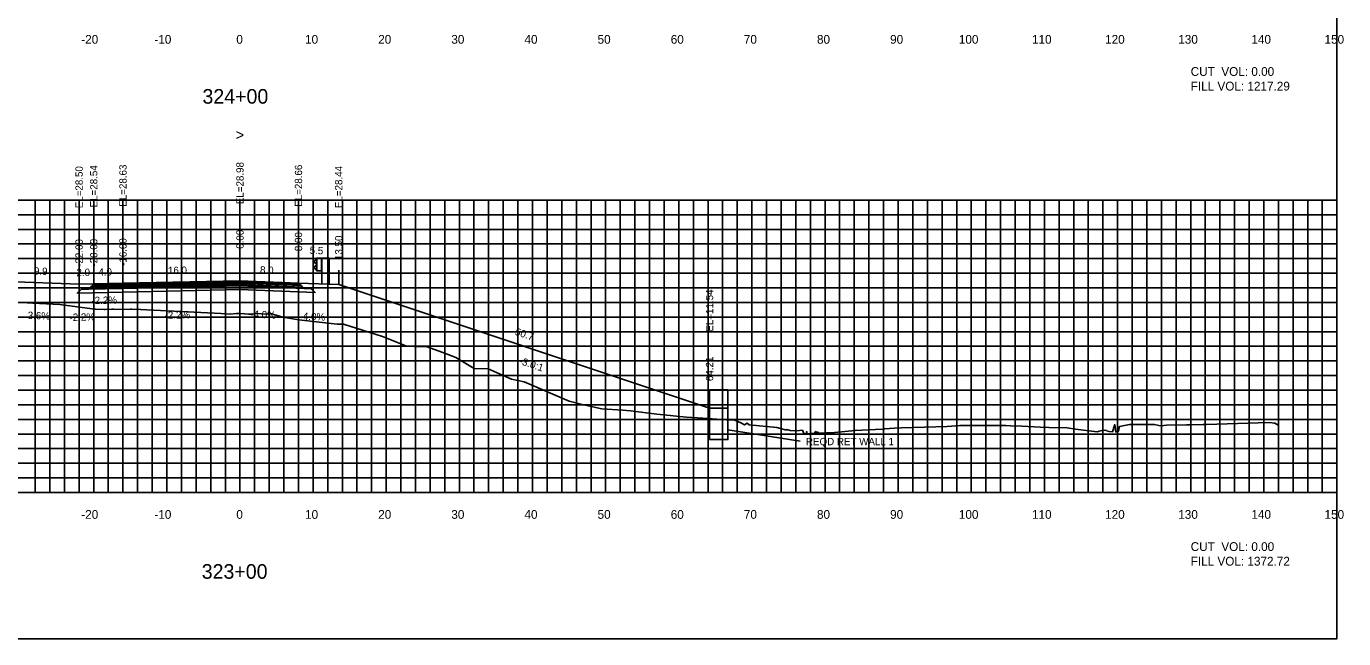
# Model space of a CAD drawing. Extents: x 1797652 to 1804145, y 245981 to 250269.
# Drawn here: x 1803621.8 to 1803801.9, y 250079.4 to 250163.2 of the extents above; entities that cross this region are included whole.
import ezdxf

# ---------------------------------------------------------------- set-up
doc = ezdxf.new("R2010")
doc.units = 0
for name, color, linetype in [('1', 7, 'Continuous'), ('10', 7, 'Continuous'), ('3', 7, 'Continuous'), ('4', 7, 'Continuous'), ('60', 7, 'Continuous'), ('ANNO-TXT', 7, 'Continuous'), ('BASE', 7, 'Continuous'), ('CL-CNST', 7, 'Continuous'), ('Level 1', 7, 'Continuous'), ('Level 62', 7, 'Continuous'), ('LOWER BINDER', 7, 'Continuous'), ('M-ROADS', 7, 'Continuous'), ('UPPER BINDER', 7, 'Continuous'), ('WEARING', 7, 'Continuous')]:
    doc.layers.add(name, color=color, linetype=linetype)

msp = doc.modelspace()

# ---------------------------------------------------------------- linework, layer by layer
for p, q in [((1803631, 250127.97), (1803631, 250129.97)), ((1803635, 250128.06), (1803635, 250130.06)), ((1803651, 250128.41), (1803651, 250130.41)), ((1803659, 250128.09), (1803659, 250130.09)), ((1803629, 250127.93), (1803629, 250129.93)), ((1803664.5, 250127.87), (1803664.5, 250129.87)), ((1803715.21, 250110.97), (1803715.21, 250112.97))]:
    msp.add_line(p, q)
msp.add_lwpolyline([(1803501, 250079.43), (1803801, 250079.43), (1803801, 250269.43), (1803501, 250269.43)], close=True)
at = {"layer": '3'}
msp.add_line((1803727.6, 250106.45), (1803717.71, 250108.02), dxfattribs=at)
at = {"layer": '60'}
for p, q in [((1803801, 250099.43), (1803801, 250139.43)), ((1803801.06, 250139.43), (1803801, 250139.43)), ((1803801.06, 250129.43), (1803801, 250129.43)), ((1803801.06, 250119.43), (1803801, 250119.43)), ((1803801.06, 250109.43), (1803801, 250109.43)), ((1803501, 250099.43), (1803801, 250099.43)), ((1803631, 250099.37), (1803631, 250099.43)), ((1803641, 250099.37), (1803641, 250099.43)), ((1803651, 250099.37), (1803651, 250099.43)), ((1803661, 250099.37), (1803661, 250099.43)), ((1803671, 250099.37), (1803671, 250099.43)), ((1803681, 250099.37), (1803681, 250099.43)), ((1803691, 250099.37), (1803691, 250099.43)), ((1803701, 250099.37), (1803701, 250099.43)), ((1803711, 250099.37), (1803711, 250099.43)), ((1803721, 250099.37), (1803721, 250099.43)), ((1803731, 250099.37), (1803731, 250099.43)), ((1803741, 250099.37), (1803741, 250099.43)), ((1803751, 250099.37), (1803751, 250099.43)), ((1803761, 250099.37), (1803761, 250099.43)), ((1803771, 250099.37), (1803771, 250099.43)), ((1803781, 250099.37), (1803781, 250099.43)), ((1803791, 250099.37), (1803791, 250099.43)), ((1803801, 250099.37), (1803801, 250099.43)), ((1803801.06, 250099.43), (1803801, 250099.43))]:
    msp.add_line(p, q, dxfattribs=at)
at = {"layer": 'BASE'}
msp.add_lwpolyline([(1803629.27, 250127.21), (1803630.27, 250127.24), (1803635, 250127.34), (1803651, 250127.69), (1803659.75, 250127.34), (1803660.75, 250127.3), (1803661.27, 250126.78), (1803651, 250127.19), (1803635, 250126.84), (1803628.75, 250126.7)], close=True, dxfattribs=at)
at = {"layer": 'CL-CNST'}
msp.add_lwpolyline([(1803619.11, 250128.28), (1803629, 250127.93), (1803631, 250127.97), (1803635, 250128.06), (1803651, 250128.41), (1803659, 250128.09), (1803664.5, 250127.87), (1803715.21, 250110.97)], dxfattribs=at)
for points in [[(1803717.71, 250110.97), (1803715.21, 250110.97), (1803715.21, 250113.47), (1803717.71, 250113.47)], [(1803715.21, 250106.68), (1803717.71, 250106.68), (1803717.71, 250110.97), (1803715.21, 250110.97)]]:
    msp.add_lwpolyline(points, close=True, dxfattribs=at)
at = {"layer": 'Level 1'}
for p, q in [((1803661.46, 250131.34), (1803661.1, 250131.04)), ((1803661.1, 250130.97), (1803661.46, 250130.68)), ((1803661.46, 250130.54), (1803661.1, 250130.24)), ((1803661.1, 250130.17), (1803661.46, 250129.89)), ((1803661.46, 250131.49), (1803661.46, 250129.74)), ((1803663.21, 250131.49), (1803661.46, 250131.49)), ((1803661.51, 250131.49), (1803661.51, 250129.74)), ((1803662.16, 250131.49), (1803662.16, 250129.74)), ((1803662.21, 250131.49), (1803662.21, 250127.96)), ((1803663.21, 250131.49), (1803663.21, 250127.92)), ((1803662.21, 250129.74), (1803661.46, 250129.74))]:
    msp.add_line(p, q, dxfattribs=at)
for centre in [(1803661.13, 250131), (1803661.13, 250130.21)]:
    msp.add_arc(centre, 0.05, 135, 226.6208, dxfattribs=at)
at = {"layer": 'Level 62'}
for p, q in [((1803501, 250139.43), (1803801, 250139.43)), ((1803623, 250099.43), (1803623, 250139.43)), ((1803625, 250099.43), (1803625, 250139.43)), ((1803627, 250099.43), (1803627, 250139.43)), ((1803629, 250099.43), (1803629, 250139.43)), ((1803631, 250099.43), (1803631, 250139.43)), ((1803633, 250099.43), (1803633, 250139.43)), ((1803635, 250099.43), (1803635, 250139.43)), ((1803637, 250099.43), (1803637, 250139.43)), ((1803639, 250099.43), (1803639, 250139.43)), ((1803641, 250099.43), (1803641, 250139.43)), ((1803643, 250099.43), (1803643, 250139.43)), ((1803645, 250099.43), (1803645, 250139.43)), ((1803647, 250099.43), (1803647, 250139.43)), ((1803649, 250099.43), (1803649, 250139.43)), ((1803651, 250099.43), (1803651, 250139.43)), ((1803653, 250099.43), (1803653, 250139.43)), ((1803655, 250099.43), (1803655, 250139.43)), ((1803657, 250099.43), (1803657, 250139.43)), ((1803659, 250099.43), (1803659, 250139.43)), ((1803661, 250099.43), (1803661, 250139.43)), ((1803663, 250099.43), (1803663, 250139.43)), ((1803665, 250099.43), (1803665, 250139.43)), ((1803667, 250099.43), (1803667, 250139.43)), ((1803669, 250099.43), (1803669, 250139.43)), ((1803671, 250099.43), (1803671, 250139.43)), ((1803673, 250099.43), (1803673, 250139.43)), ((1803675, 250099.43), (1803675, 250139.43)), ((1803677, 250099.43), (1803677, 250139.43)), ((1803679, 250099.43), (1803679, 250139.43)), ((1803681, 250099.43), (1803681, 250139.43)), ((1803683, 250099.43), (1803683, 250139.43)), ((1803685, 250099.43), (1803685, 250139.43)), ((1803687, 250099.43), (1803687, 250139.43)), ((1803689, 250099.43), (1803689, 250139.43)), ((1803691, 250099.43), (1803691, 250139.43)), ((1803693, 250099.43), (1803693, 250139.43)), ((1803695, 250099.43), (1803695, 250139.43)), ((1803697, 250099.43), (1803697, 250139.43)), ((1803699, 250099.43), (1803699, 250139.43)), ((1803701, 250099.43), (1803701, 250139.43)), ((1803703, 250099.43), (1803703, 250139.43)), ((1803705, 250099.43), (1803705, 250139.43)), ((1803707, 250099.43), (1803707, 250139.43)), ((1803709, 250099.43), (1803709, 250139.43)), ((1803711, 250099.43), (1803711, 250139.43)), ((1803713, 250099.43), (1803713, 250139.43)), ((1803715, 250099.43), (1803715, 250139.43)), ((1803717, 250099.43), (1803717, 250139.43)), ((1803719, 250099.43), (1803719, 250139.43)), ((1803721, 250099.43), (1803721, 250139.43)), ((1803723, 250099.43), (1803723, 250139.43)), ((1803725, 250099.43), (1803725, 250139.43)), ((1803727, 250099.43), (1803727, 250139.43)), ((1803729, 250099.43), (1803729, 250139.43)), ((1803731, 250099.43), (1803731, 250139.43)), ((1803733, 250099.43), (1803733, 250139.43)), ((1803735, 250099.43), (1803735, 250139.43)), ((1803737, 250099.43), (1803737, 250139.43)), ((1803739, 250099.43), (1803739, 250139.43)), ((1803741, 250099.43), (1803741, 250139.43)), ((1803743, 250099.43), (1803743, 250139.43)), ((1803745, 250099.43), (1803745, 250139.43)), ((1803747, 250099.43), (1803747, 250139.43)), ((1803749, 250099.43), (1803749, 250139.43)), ((1803751, 250099.43), (1803751, 250139.43)), ((1803753, 250099.43), (1803753, 250139.43)), ((1803755, 250099.43), (1803755, 250139.43)), ((1803757, 250099.43), (1803757, 250139.43)), ((1803759, 250099.43), (1803759, 250139.43)), ((1803761, 250099.43), (1803761, 250139.43)), ((1803763, 250099.43), (1803763, 250139.43)), ((1803765, 250099.43), (1803765, 250139.43)), ((1803767, 250099.43), (1803767, 250139.43)), ((1803769, 250099.43), (1803769, 250139.43)), ((1803771, 250099.43), (1803771, 250139.43)), ((1803773, 250099.43), (1803773, 250139.43)), ((1803775, 250099.43), (1803775, 250139.43)), ((1803777, 250099.43), (1803777, 250139.43)), ((1803779, 250099.43), (1803779, 250139.43)), ((1803781, 250099.43), (1803781, 250139.43)), ((1803783, 250099.43), (1803783, 250139.43)), ((1803785, 250099.43), (1803785, 250139.43)), ((1803787, 250099.43), (1803787, 250139.43)), ((1803789, 250099.43), (1803789, 250139.43)), ((1803791, 250099.43), (1803791, 250139.43)), ((1803793, 250099.43), (1803793, 250139.43)), ((1803795, 250099.43), (1803795, 250139.43)), ((1803797, 250099.43), (1803797, 250139.43)), ((1803799, 250099.43), (1803799, 250139.43)), ((1803801, 250099.43), (1803801, 250139.43)), ((1803501, 250137.43), (1803801, 250137.43)), ((1803501, 250135.43), (1803801, 250135.43)), ((1803501, 250133.43), (1803801, 250133.43)), ((1803501, 250131.43), (1803801, 250131.43)), ((1803501, 250129.43), (1803801, 250129.43)), ((1803501, 250127.43), (1803801, 250127.43)), ((1803501, 250125.43), (1803801, 250125.43)), ((1803501, 250123.43), (1803801, 250123.43)), ((1803501, 250121.43), (1803801, 250121.43)), ((1803501, 250119.43), (1803801, 250119.43)), ((1803501, 250117.43), (1803801, 250117.43)), ((1803501, 250115.43), (1803801, 250115.43)), ((1803501, 250113.43), (1803801, 250113.43)), ((1803501, 250111.43), (1803801, 250111.43)), ((1803501, 250109.43), (1803801, 250109.43)), ((1803501, 250107.43), (1803801, 250107.43)), ((1803501, 250105.43), (1803801, 250105.43)), ((1803501, 250103.43), (1803801, 250103.43)), ((1803501, 250101.43), (1803801, 250101.43)), ((1803501, 250099.43), (1803801, 250099.43))]:
    msp.add_line(p, q, dxfattribs=at)
at = {"layer": 'LOWER BINDER'}
for points in [[(1803635, 250127.53), (1803651, 250127.88), (1803659.55, 250127.54), (1803659.75, 250127.34), (1803651, 250127.69), (1803635, 250127.34), (1803630.27, 250127.24), (1803630.46, 250127.43)], [(1803635, 250127.72), (1803651, 250128.07), (1803659.36, 250127.74), (1803659.55, 250127.54), (1803651, 250127.88), (1803635, 250127.53), (1803630.46, 250127.43), (1803630.65, 250127.62)]]:
    msp.add_lwpolyline(points, close=True, dxfattribs=at)
at = {"layer": 'M-ROADS'}
msp.add_lwpolyline([(1803617.94, 250125.62), (1803622.69, 250125.34), (1803626.38, 250125.15), (1803630.8, 250124.58), (1803631.2, 250124.53), (1803631.24, 250124.53), (1803632.45, 250124.47), (1803632.57, 250124.48), (1803633.5, 250124.52), (1803633.7, 250124.53), (1803634.94, 250124.47), (1803634.95, 250124.47), (1803636.05, 250124.53), (1803636.2, 250124.53), (1803637.39, 250124.48), (1803637.45, 250124.47), (1803638.27, 250124.43), (1803648.42, 250123.92), (1803649.05, 250123.87), (1803649.67, 250123.81), (1803650.51, 250123.9), (1803650.9, 250123.92), (1803651.64, 250123.86), (1803652.15, 250123.81), (1803652.7, 250123.84), (1803653.42, 250123.92), (1803653.95, 250123.88), (1803654.67, 250123.81), (1803655.18, 250123.9), (1803656.86, 250123.42), (1803659.03, 250123.04), (1803664.31, 250122.47), (1803664.74, 250122.47), (1803665.15, 250122.47), (1803670.47, 250120.79), (1803673.7, 250119.49), (1803674.81, 250119.42), (1803675.61, 250119.42), (1803676.45, 250119.42), (1803678.74, 250118.57), (1803680.52, 250117.9), (1803683.02, 250116.4), (1803684.95, 250116.33), (1803688.14, 250114.93), (1803689.84, 250114.55), (1803696, 250111.91), (1803697.77, 250111.45), (1803700.47, 250110.9), (1803703.35, 250110.7), (1803704.4, 250110.62), (1803708, 250110.16), (1803712.06, 250109.76), (1803714.28, 250109.61), (1803717.49, 250109.38), (1803718.58, 250109.38), (1803719.56, 250108.9), (1803719.99, 250108.69), (1803720.34, 250108.91), (1803720.62, 250108.69), (1803724.43, 250108.34), (1803725.73, 250107.96), (1803725.77, 250108.06), (1803726.23, 250107.92), (1803727.08, 250107.87), (1803727.91, 250107.96), (1803728.12, 250107.49), (1803728.44, 250107.47), (1803728.5, 250107.76), (1803728.51, 250107.48), (1803728.53, 250107.44), (1803729.13, 250107.49), (1803729.55, 250107.5), (1803729.68, 250107.78), (1803729.9, 250107.57), (1803729.98, 250107.72), (1803730.1, 250107.55), (1803732.28, 250107.66), (1803735.1, 250107.93), (1803737.89, 250108.04), (1803738.99, 250108.09), (1803739.12, 250108.14), (1803740.5, 250108.22), (1803741.44, 250108.27), (1803744.6, 250108.37), (1803747.68, 250108.48), (1803749.44, 250108.58), (1803754.15, 250108.58), (1803754.99, 250108.58), (1803755.48, 250108.59), (1803755.69, 250108.6), (1803755.69, 250108.6), (1803755.7, 250108.6), (1803755.72, 250108.6), (1803756.37, 250108.53), (1803757.91, 250108.49), (1803760.42, 250108.35), (1803761.58, 250108.33), (1803764.1, 250108.3), (1803765.23, 250108.1), (1803768.2, 250107.74), (1803768.49, 250107.81), (1803768.86, 250107.92), (1803769.26, 250107.97), (1803769.48, 250107.9), (1803769.5, 250107.88), (1803769.84, 250107.79), (1803770.3, 250107.73), (1803770.59, 250108.58), (1803770.62, 250108.72), (1803770.64, 250108.67), (1803770.75, 250107.71), (1803770.76, 250107.73), (1803770.79, 250107.75), (1803771.09, 250107.76), (1803771.14, 250107.87), (1803771.18, 250107.99), (1803771.23, 250108.31), (1803771.27, 250108.48), (1803772.65, 250108.72), (1803772.93, 250108.72), (1803774.21, 250108.72), (1803774.93, 250108.72), (1803775.69, 250108.72), (1803776.07, 250108.72), (1803776.63, 250108.61), (1803776.97, 250108.54), (1803777.68, 250108.64), (1803780.44, 250108.71), (1803780.97, 250108.71), (1803781, 250108.68), (1803781.06, 250108.71), (1803782.68, 250108.75), (1803783.14, 250108.75), (1803790.22, 250108.95), (1803791.82, 250108.99), (1803792.42, 250108.91), (1803792.51, 250108.91), (1803792.96, 250108.65)], dxfattribs=at)
at = {"layer": 'UPPER BINDER'}
msp.add_lwpolyline([(1803659.36, 250127.74), (1803659.16, 250127.94), (1803651, 250128.26), (1803635, 250127.91), (1803630.85, 250127.82), (1803630.65, 250127.62), (1803635, 250127.72), (1803651, 250128.07)], close=True, dxfattribs=at)
at = {"layer": 'WEARING'}
msp.add_lwpolyline([(1803659.16, 250127.94), (1803659, 250128.09), (1803651, 250128.41), (1803635, 250128.06), (1803631, 250127.97), (1803630.85, 250127.82), (1803635, 250127.91), (1803651, 250128.26)], close=True, dxfattribs=at)

# ---------------------------------------------------------------- texts
msp.add_text('-3.0:1', height=1, rotation=341.5652).set_placement((1803689.07, 250117.05))
at = {"layer": '1'}
for s, p in [('324+00', (1803645.87, 250152.63)), ('323+00', (1803645.77, 250087.63))]:
    msp.add_text(s, height=2, dxfattribs=at).set_placement(p)
at = {"layer": '10'}
for s, p in [('-20', (1803629.3, 250160.83)), ('-10', (1803639.3, 250160.83)), ('0', (1803650.5, 250160.83)), ('10', (1803659.9, 250160.83)), ('20', (1803669.9, 250160.83)), ('30', (1803679.9, 250160.83)), ('40', (1803689.9, 250160.83)), ('50', (1803699.9, 250160.83)), ('60', (1803709.9, 250160.83)), ('70', (1803719.9, 250160.83)), ('80', (1803729.9, 250160.83)), ('90', (1803739.9, 250160.83)), ('100', (1803749.3, 250160.83)), ('110', (1803759.3, 250160.83)), ('120', (1803769.3, 250160.83)), ('130', (1803779.3, 250160.83)), ('140', (1803789.3, 250160.83)), ('150', (1803799.3, 250160.83)), ('-20', (1803629.3, 250095.83)), ('-10', (1803639.3, 250095.83)), ('0', (1803650.5, 250095.83)), ('10', (1803659.9, 250095.83)), ('20', (1803669.9, 250095.83)), ('30', (1803679.9, 250095.83)), ('40', (1803689.9, 250095.83)), ('50', (1803699.9, 250095.83)), ('60', (1803709.9, 250095.83)), ('70', (1803719.9, 250095.83)), ('80', (1803729.9, 250095.83)), ('90', (1803739.9, 250095.83)), ('100', (1803749.3, 250095.83)), ('110', (1803759.3, 250095.83)), ('120', (1803769.3, 250095.83)), ('130', (1803779.3, 250095.83)), ('140', (1803789.3, 250095.83)), ('150', (1803799.3, 250095.83))]:
    msp.add_text(s, height=1.2, dxfattribs=at).set_placement(p)
at = {"layer": '3'}
for s, p in [('EL=28.98', (1803651.5, 250138.88)), ('EL=28.50', (1803629.5, 250138.32)), ('EL=28.54', (1803631.5, 250138.44)), ('EL=28.63', (1803635.5, 250138.53)), ('EL=28.66', (1803659.5, 250138.52)), ('EL=28.44', (1803665, 250138.34)), ('-22.00', (1803629.5, 250130.31)), ('-20.00', (1803631.5, 250130.35)), ('-16.00', (1803635.5, 250130.44)), ('0.00', (1803651.5, 250132.77)), ('8.00', (1803659.5, 250132.45)), ('13.50', (1803665, 250131.24)), ('EL=11.54', (1803715.71, 250121.44)), ('64.21', (1803715.71, 250114.67))]:
    msp.add_text(s, height=1, rotation=90, dxfattribs=at).set_placement(p)
msp.add_text('REQD RET WALL 1', height=1, dxfattribs=at).set_placement((1803728.39, 250105.9))
at = {"layer": '4'}
for s, rotation, p in [('5.5', 357.7094, (1803660.51, 250132.08)), ('9.9', 357.9508, (1803622.81, 250129.25)), ('2.0', 1.2603, (1803628.65, 250129.02)), ('4.0', 1.2603, (1803631.65, 250129.09)), ('16.0', 1.2603, (1803641.16, 250129.3)), ('8.0', 357.7094, (1803653.72, 250129.4)), ('-2.2%', 1.2603, (1803630.7, 250125.2)), ('3.6%', 357.9508, (1803621.96, 250123.18)), ('-2.2%', 1.2603, (1803627.7, 250122.9)), ('-2.2%', 1.2603, (1803640.7, 250123.18)), ('-4.0%', 357.7094, (1803652.39, 250123.35)), ('-4.0%', 357.7094, (1803659.14, 250123.08)), ('50.7', 341.5652, (1803688.52, 250121.03))]:
    msp.add_text(s, height=1, rotation=rotation, dxfattribs=at).set_placement(p)
at = {"layer": '60'}
msp.add_text('>', height=1.5, dxfattribs=at).set_placement((1803650.39, 250147.62))
at = {"layer": 'ANNO-TXT'}
for s, p in [('CUT  VOL: 0.00', (1803781, 250156.43)), ('FILL VOL: 1217.29', (1803781, 250154.43)), ('CUT  VOL: 0.00', (1803781, 250091.43)), ('FILL VOL: 1372.72', (1803781, 250089.43))]:
    msp.add_text(s, height=1.2, dxfattribs=at).set_placement(p)

doc.saveas('drawing.dxf')
